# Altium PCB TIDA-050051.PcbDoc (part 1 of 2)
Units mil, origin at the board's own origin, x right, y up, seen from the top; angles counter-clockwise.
Board outline 1055.12 x 796.27 mil, 6 copper layers (Top Layer, Signal Layer 1, Signal Layer 2, Signal Layer 3, Signal Layer 4, Bottom Layer), stack 61 mil thick; 108 components, 65 nets, 370 pads, 157 vias.
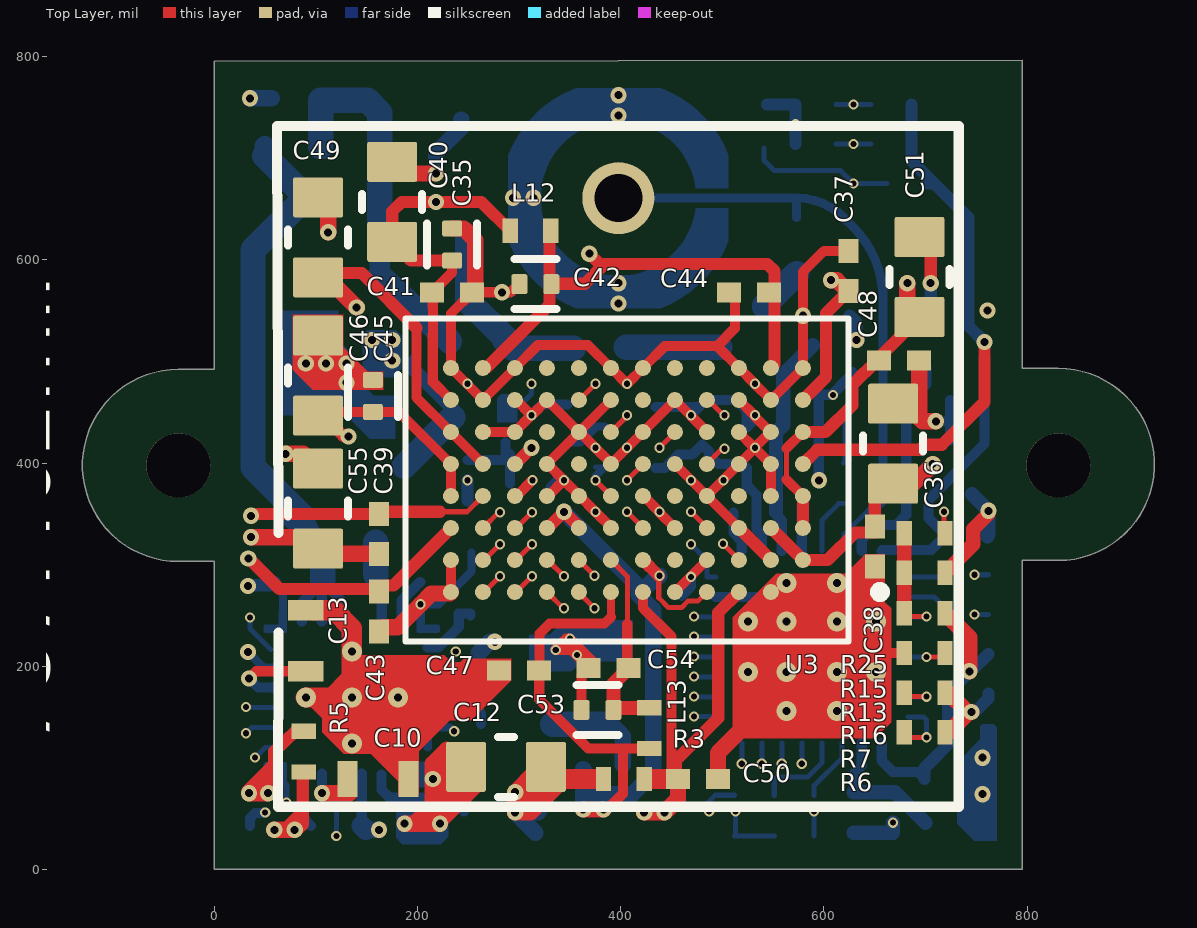
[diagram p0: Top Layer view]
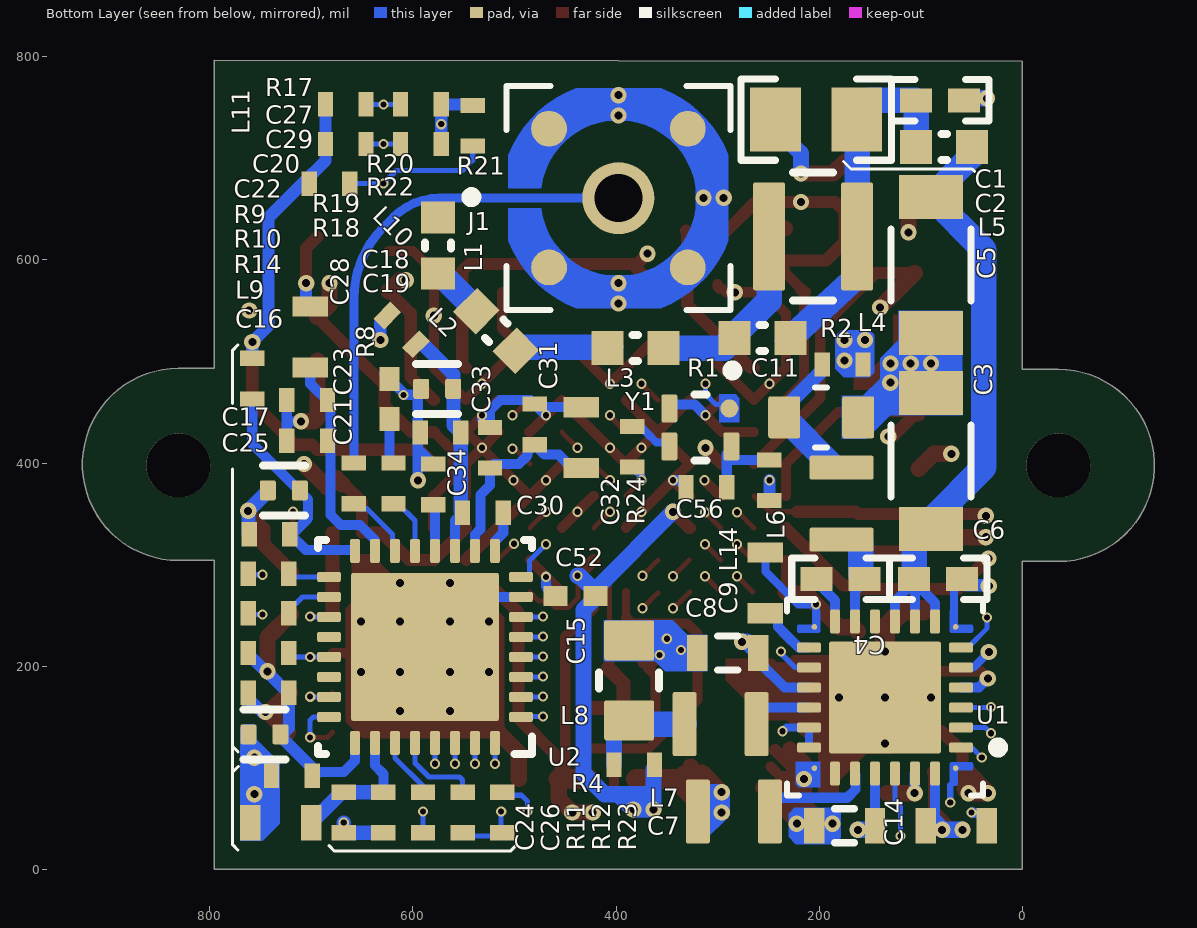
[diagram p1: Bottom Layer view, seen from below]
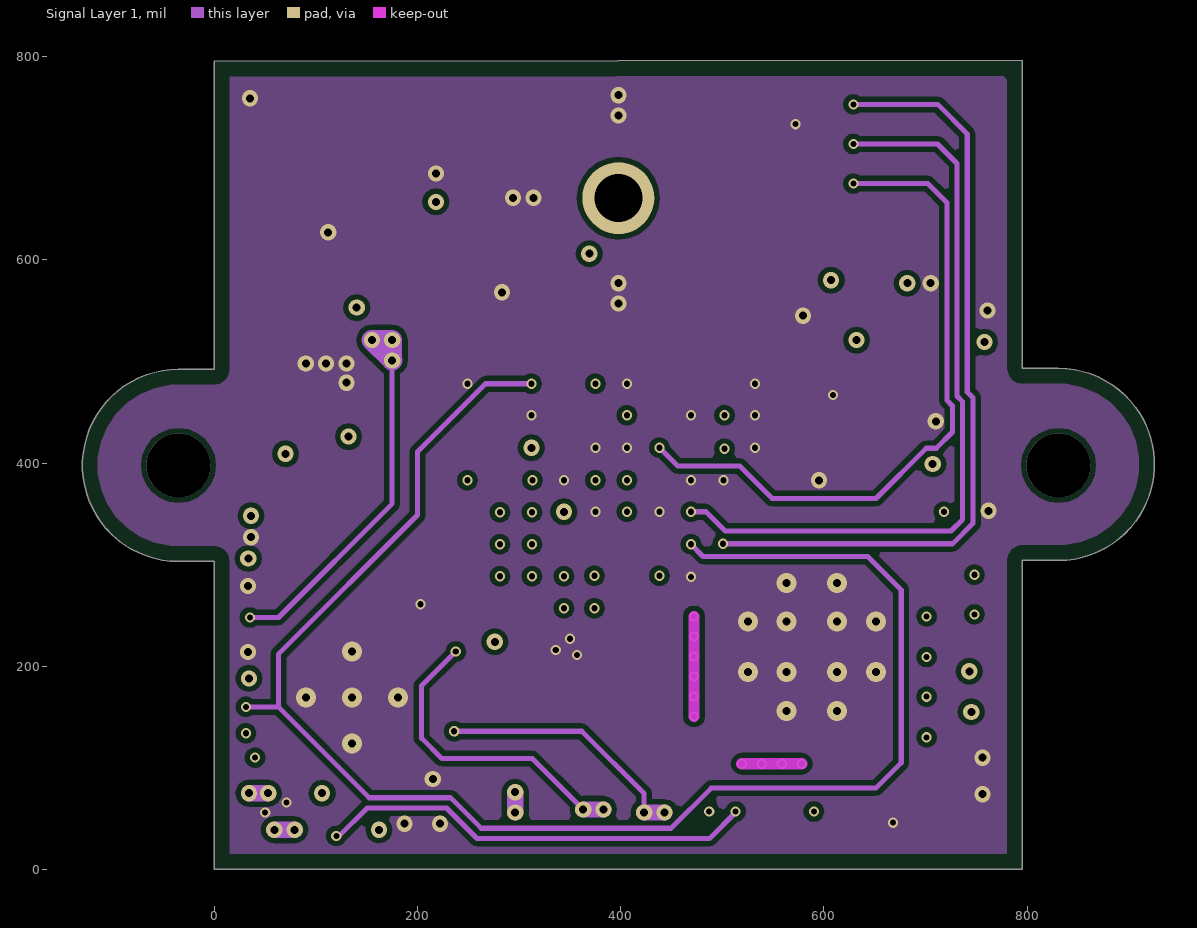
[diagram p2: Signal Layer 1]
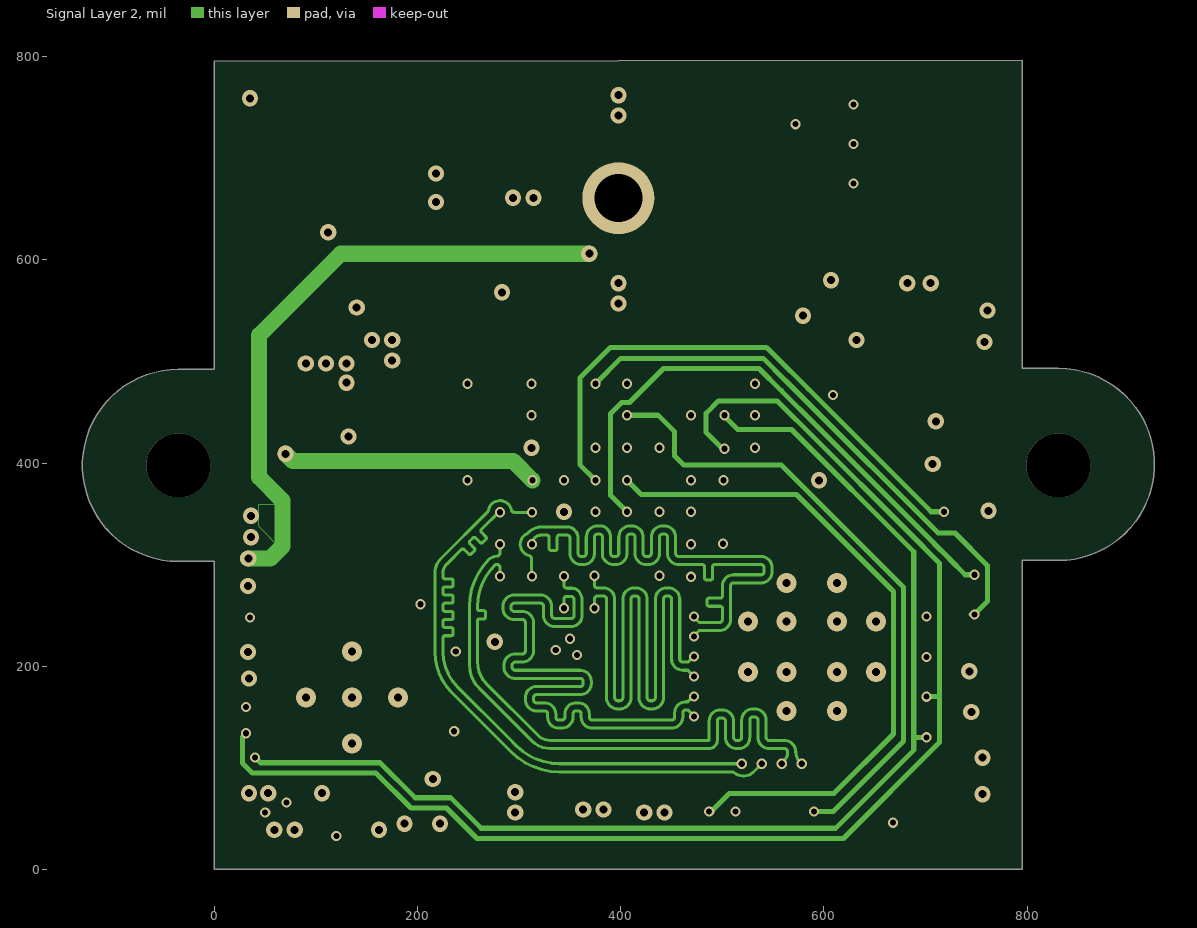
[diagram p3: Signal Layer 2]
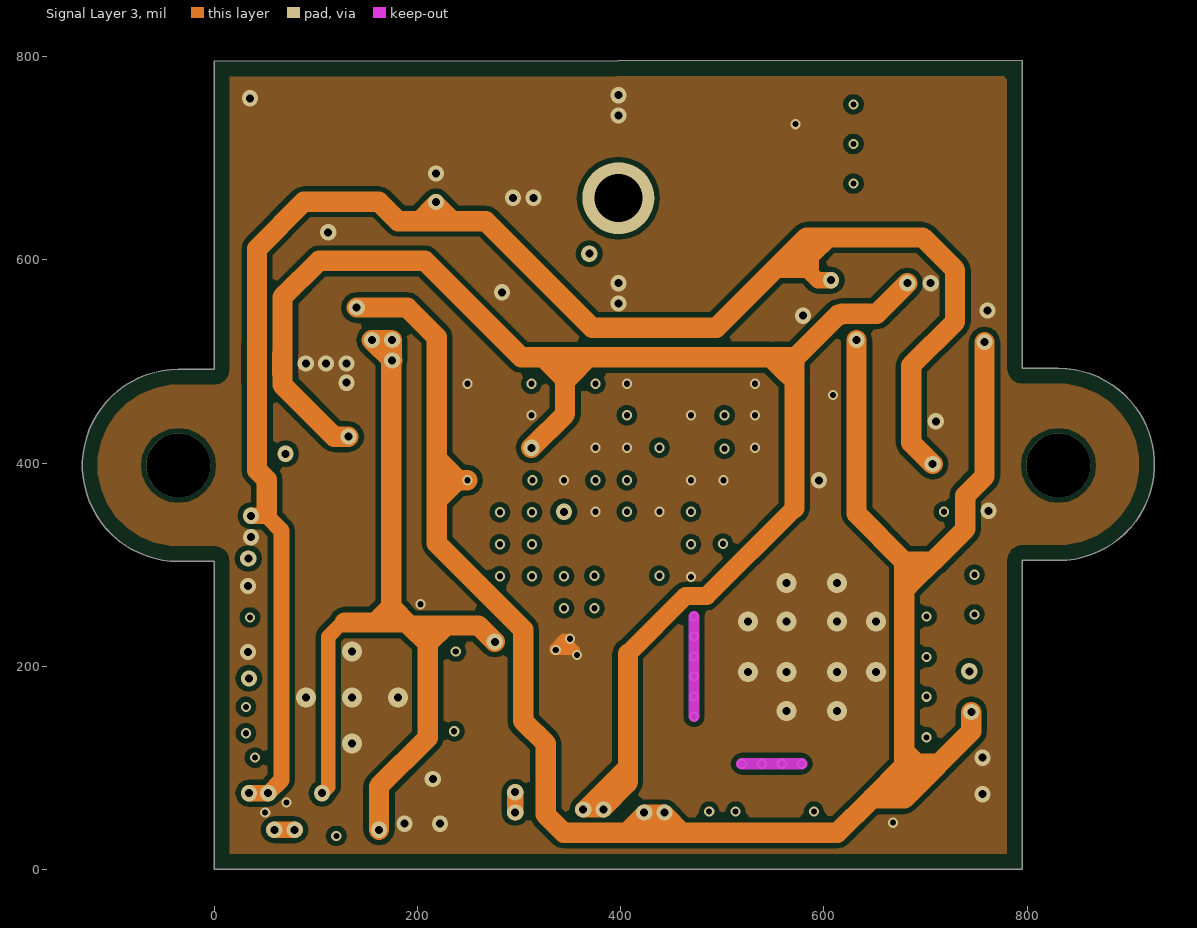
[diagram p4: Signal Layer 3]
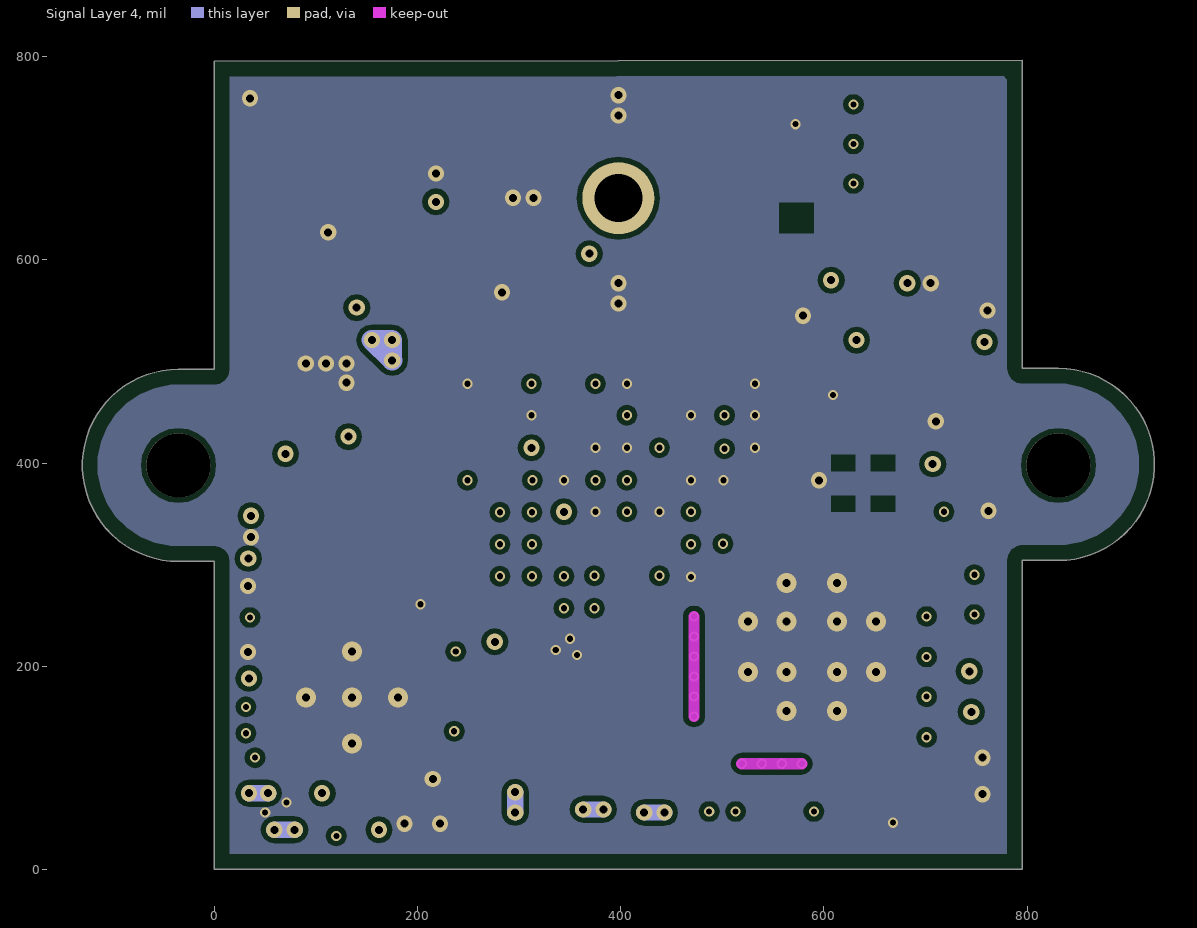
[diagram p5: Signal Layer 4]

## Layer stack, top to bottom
Top Solder: solder mask 0.5, Solder Resist, Dk 3.5
Top Layer: signal copper 1.4
Dielectric 1: prepreg 5.1, FR-4 High Tg, Dk 4.2
Signal Layer 1: signal copper 1.4
Dielectric 2: core 8, FR-4 High Tg, Dk 4.2
Signal Layer 2: signal copper 1.4
Dielectric 4: core 26.4, FR-4 High Tg, Dk 4.2
Signal Layer 3: signal copper 1.4
Dielectric 5: core 8, FR-4 High Tg, Dk 4.2
Signal Layer 4: signal copper 1.4
Dielectric 3: prepreg 5.1, FR-4 High Tg, Dk 4.2
Bottom Layer: signal copper 1.4
Bottom Solder: solder mask 0.5, Solder Resist, Dk 3.5

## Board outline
0,0 0,303.15 -35.43,303.15 cw(c-35.43,397.64) -35.43,492.13 0,492.13 0,795.28 795.28,796.27 795.28,493.11 830.71,493.11 cw(c830.71,398.62) 830.71,304.14 795.3,304.14 795.28,0.99 795.28,0

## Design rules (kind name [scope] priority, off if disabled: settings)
AcuteAngle [All] p1: minimum=4.50000000000000E+0001 checktracksonly=FALSE
AssemblyTestPointUsage [All] p1: valid=2
BoardOutlineClearance BoardOutlineClearance_MountingHoles [OnCopper and InComponentClass('Mounting Holes')] p1: gap=39.37 ignorepadtopadclearanceinfootprint=FALSE
BoardOutlineClearance BoardOutlineClearance_Poly [OnCopper and IsPoly] p2: gap=15 ignorepadtopadclearanceinfootprint=FALSE
BoardOutlineClearance [OnCopper and Not InComponentClass('Logo') and not InComponentClass('FiducialMark') and not InRegion(1000,500,4000,800) and not InPoly] p3: gap=25 ignorepadtopadclearanceinfootprint=FALSE
Clearance Clearance_Signal_Layer_1 [InPolygon And (OnLayer('Signal Layer 2'))] p1: gap=5 ignorepadtopadclearanceinfootprint=TRUE except(10: Arc-Arc Arc-Track Arc-SMDPad Arc-THPad Arc-Via Arc-Fill Arc-Poly Arc-Region Arc-Text Arc-Hole Track-Track Track-SMDPad Track-THPad Track-Via Track-Fill Track-Poly Track-Region Track-Text Track-Hole)
Clearance Clearance_Keepouts [((IsTrack Or IsArc) And Not InPoly) And IsFree and IsKeepOut vs ((IsTrack Or IsArc) And Not InPoly) And IsFree and IsKeepOut] p2: gap=0 ignorepadtopadclearanceinfootprint=FALSE
Clearance Clearance_Poly [InPolygon] p3: gap=5 ignorepadtopadclearanceinfootprint=TRUE
Clearance Clearance_FiducialMark [IsKeepOut and InComponentClass('FiducialMark') vs IsPad and InComponentClass('FiducialMark')] p4: gap=0 ignorepadtopadclearanceinfootprint=FALSE
Clearance [All] p5: gap=5 ignorepadtopadclearanceinfootprint=TRUE
ComponentClearance ComponentClearance_MountingHoles_FiducialMarks [InComponentClass('Mounting Holes') vs InComponentClass('FiducialMark')] p1: gap=50 collisioncheckmode=3 verticalgap=10 showdistances=FALSE
ComponentClearance ComponentClearance_Shunt [InComponentClass('Header') vs InComponentClass('Shunt')] p2: gap=0 collisioncheckmode=3 verticalgap=0 showdistances=FALSE
ComponentClearance ComponentClearance_Logo [InComponentClass('Logo')] p3: gap=30 collisioncheckmode=3 verticalgap=10 showdistances=FALSE
ComponentClearance ComponentClearance_ScrewToNut [(HasFootprint('NY PMS 440 0025 PH')) vs (HasFootprint('Keystone_1902C'))] p4: gap=5 collisioncheckmode=3 verticalgap=10 showdistances=FALSE
ComponentClearance ComponentClearance_MountingHoles [InComponentClass('Mounting Holes')] p5: gap=100 collisioncheckmode=3 verticalgap=100000 showdistances=FALSE
ComponentClearance ComponentClearance_SmallPassives [HasFootprint('0201*') or HasFootprint('0402*') or HasFootprint('0508') or HasFootprint('0603*') or HasFootprint('0612') or HasFootprint('0805*') or HasFootprint('0815*') or HasFootprint('0830*') or HasFootprint('1206*') or HasFootprint('1210*') or HasFootprint('1808*') or HasFootprint('1812*') or HasFootprint('1825*') or HasFootprint('2010*') or HasFootprint('2220*') or HasFootprint('2225*') or HasFootprint('2512*') or HasFootprint('2728*') or HasFootprint('3518*') vs HasFootprint('0201*') or HasFootprint('0402*') or HasFootprint('0508') or HasFootprint('0603*') or HasFootprint('0612') or HasFootprint('0805*') or HasFootprint('0815*') or HasFootprint('0830*') or HasFootprint('1206*') or HasFootprint('1210*') or HasFootprint('1808*') or HasFootprint('1812*') or HasFootprint('1825*') or HasFootprint('2010*') or HasFootprint('2220*') or HasFootprint('2225*') or HasFootprint('2512*') or HasFootprint('2728*') or HasFootprint('3518*')] p6: gap=14.96 collisioncheckmode=3 verticalgap=10 showdistances=FALSE
ComponentClearance ComponentClearance_THtoSMT [IsThruComponent vs IsSMTComponent] p7: gap=20 collisioncheckmode=3 verticalgap=30 showdistances=FALSE
ComponentClearance ComponentClearance_THtoTH [IsThruComponent vs IsThruComponent] p8: gap=20 collisioncheckmode=3 verticalgap=30 showdistances=FALSE
ComponentClearance [All] p9: gap=15 collisioncheckmode=3 verticalgap=10 showdistances=FALSE
DiffPairsRouting [All] p1: maxlimit=100 minlimit=5 mostfreqgap=10 toplayer_minwidth=3 toplayer_maxwidth=15 toplayer_prefwidth=5 midlayer1_minwidth=3 midlayer1_maxwidth=15 midlayer1_prefwidth=5 midlayer2_minwidth=3 midlayer2_maxwidth=15 midlayer2_prefwidth=5 midlayer3_minwidth=3 midlayer3_maxwidth=15 midlayer3_prefwidth=5 midlayer4_minwidth=3 midlayer4_maxwidth=15 midlayer4_prefwidth=5 bottomlayer_minwidth=3 bottomlayer_maxwidth=15 bottomlayer_prefwidth=5 maxuncoupledlength=1000
FabricationTestPointUsage TestPointUsage [All] p1: valid=2 allowmultiple=FALSE
FabricationTestpoint Testpoint [All] p1: side=3 testpointundercomponent=TRUE minsize=40 maxsize=100 preferedsize=60 minholesize=0 maxholesize=40 preferedholesize=32 testpointgrid=1 allowsidetop=TRUE allowsidebottom=TRUE usegrid=TRUE gridtolerance=0.01
FanoutControl Fanout_LCC [IsLCC] p1: bgadir=Out bgaviamode=Centered fanoutstyle=Auto fanoutdirection=Alternating viagrid=1 // Fanout_LCC (Default Rule)
FanoutControl Fanout_BGA [IsBGA] p2: bgadir=Out bgaviamode=Centered fanoutstyle=Auto fanoutdirection=Alternating viagrid=1 // Fanout_BGA (Default Rule)
FanoutControl Fanout_Default [All] p4: bgadir=Out bgaviamode=Centered fanoutstyle=Auto fanoutdirection=Alternating viagrid=1 // Fanout_Default (Default Rule)
FanoutControl Fanout_Small [(CompPinCount < 5)] p5: bgadir=Out bgaviamode=Centered fanoutstyle=Auto fanoutdirection=OutThenIn viagrid=1 // Fanout_Small (Default Rule)
HoleSize [All] p1: absolutevalues=TRUE maxlimit=251 minlimit=6 maxpercent=80.000 minpercent=20.000
MinimumAnnularRing MinimumAnnularRing_ThermalPadVias [IsVia and InAnyComponent] p1: minimumring=5.91
MinimumAnnularRing [All] p2: minimumring=2
MinimumSolderMaskSliver MinimumSolderMaskSliver_Logo [InComponentClass('Logo') vs InComponentClass('Logo')] p1: minsoldermaskwidth=0.7
MinimumSolderMaskSliver [All] p2: minsoldermaskwidth=3.94
PlaneConnect [All] p1: planeconnectstyle=Direct reliefexpansion=10 reliefentries=4 reliefconductorwidth=10 reliefairgap=10
PolygonConnect [All] p1: connectstyle=Direct reliefconductorwidth=10 reliefentries=4 polygonreliefangle="90 Angle" airgapwidth=10
RoutingVias ThermalPadVias [IsVia and InAnyComponent] p1: holewidth=7.87 width=19.68 viastyle="Through Hole" minholewidth=7.87 minwidth=19.68 maxholewidth=12.99 maxwidth=23.62
RoutingVias [All] p2: holewidth=16 width=34 viastyle="Through Hole" minholewidth=6 minwidth=10 maxholewidth=40 maxwidth=65
SilkToBoardRegionClearance [Not ((IsComment or IsDesignator) And (Hide <> 'False')) and not InRegion(1000,500,4000,800)] p1:
SilkToSilkClearance SilkToSilkClearance_Pb-FreeLogo [(HasFootprint('Pb-Free_Overlay_Medium') OR HasFootprint('Pb-Free_Overlay_Small')) vs (HasFootprint('Pb-Free_Overlay_Medium') OR HasFootprint('Pb-Free_Overlay_Small'))] p1: silktosilkclearance=0
SilkToSilkClearance [All] p2: silktosilkclearance=3
SilkToSolderMaskClearance SilkToComponentPadClearance [(IsPad or IsFill or IsRegion) and InAnycomponent] p1: minsilkscreentomaskgap=0 clearancetoexposedcopper=TRUE
SilkToSolderMaskClearance "Silk to Solder Mask Opening" [All] p2: minsilkscreentomaskgap=0 clearancetoexposedcopper=FALSE
SolderMaskExpansion [All] p1: expansion=1.97
UnRoutedNet [All] p1: checkbadconnections=TRUE
Width [All] p1: maxlimit=100 minlimit=5 preferedwidth=10 minimp=50.000000 maximp=50.000000 favimp=50.000000 checkconnectedcopper=TRUE
14 further rules are at their usual default settings.

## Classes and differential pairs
component class Serializer: C16 C17 C18 C19 C20 C21 C22 C23 C24 C25 C26 C27 C28 C29 C30 C31 C32 C33 C34 L9 L10 L11 R6 R7 R8 R9 R10 R11 R12 R13 R14 R15 R16 U2
component class Imager: C35 C36 C37 C38 C39 C40 C41 C42 C43 C44 C45 C46 C47 C48 C49 C50 C51 C52 C53 C54 C55 C56 L12 L13 L14 R17 R18 R19 R20 R21 R22 R23 R24 R25 U3 Y1
component class PMIC: C1 C2 C3 C4 C5 C6 C7 C8 C9 C10 C11 C12 C13 C14 C15 J1 L1 L2 L3 L4 L5 L6 L7 L8 R1 R2 R3 R4 R5 U1
component class Hardware: FID1 FID2 FID3 Logo2 ZZ1 ZZ2 ZZ3
component class FiducialMark: FID1 FID2 FID3
component class AssemblyNote: ZZ1 ZZ2 ZZ3
differential pair CSI0_D3: +CSI0_D3_P -CSI0_D3_N
differential pair CSI0_D2: +CSI0_D2_P -CSI0_D2_N
differential pair CSI0_D1: +CSI0_D1_P -CSI0_D1_N
differential pair CSI0_D0: +CSI0_D0_P -CSI0_D0_N
differential pair CSI0_CLK: +CSI0_CLK_P -CSI0_CLK_N

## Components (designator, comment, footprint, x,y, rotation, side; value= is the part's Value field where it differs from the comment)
C1 "Capacitor" 0805_HV 203,738 r0 bottom value=4.7uF
C2 "CGA2B3X7R1H104M050BB" 0402 81,757 r180 bottom value=0.1uF
C3 "C3216X7R1E106M160AE" 1206_190 90,402 r90 bottom value=10uF
C4 "CGA2B3X7R1H104M050BB" 0402 179,286 r0 bottom value=0.1uF
C5 "C1206C106J3RACAUTO" 1206_180 90,595 r270 bottom value=10uF
C6 "CGA2B3X7R1H104M050BB" 0402 83,286 r180 bottom value=0.1uF
C7 "GRM188Z71A106KA73D" 0603S 175,43 r0 bottom
C8 "GRM188Z71A106KA73D" 0603S 290,213 r0 bottom
C9 "LMK107B7105KAHT" 0603S 253,282 r270 bottom value=1uF
C10 "GCM188R70J225KE22D" 0603S 161,89 r0 top value=2.2uF
C11 "CGA4J3X7S1A106K125AE" FP-CGA4J3X7S1A106K125AE_0805-MFG 198,445 r0 bottom
C12 "JMJ212CB7106KGHT" 0805_HV1 287,101 r180 top value=10uF
C13 "LMK107B7105KAHT" 0603S 90,225 r90 top value=1uF
C14 "GCM188R70J225KE22D" 0603S 65,43 r180 bottom value=2.2uF
C15 "JMJ212CB7106KGHT" 0805_HV1 387,186 r90 bottom value=10uF
C16 "GRT155R70J105KE01D" FP-GRT155R70J105KE01D_0402-MFG 746,133 r180 bottom
C17 "GRM155R71C103KA01D" 0402S 719,92 r0 bottom value=0.01uF
C18 "GRT155R70J105KE01D" FP-GRT155R70J105KE01D_0402-MFG 576,473 r180 bottom
C19 "GRM155R71C103KA01D" 0402S 572.72,430 r0 bottom value=0.01uF
C20 "GRT155R70J105KE01D" FP-GRT155R70J105KE01D_0402-MFG 727,373 r180 bottom
C21 "CGA2B3X7R1H333K050BB" 0402S 658,380 r270 bottom value=0.033uF
C22 "GRM155R71C103KA01D" 0402S 741,330 r0 bottom value=0.01uF
C23 "CGA2B3X7R1H153K050BB" 0402S 619,380 r270 bottom value=0.015uF
C24 "0402YC104KAT2A" 0402S 668,56 r270 bottom value=0.1uF
C25 "GRM188Z71A106MA73D" 0603S 730,46 r180 bottom value=10uF
C26 "GRM155R71C103KA01D" 0402S 629,56 r270 bottom value=0.01uF
C27 "0402YC104KAT2A" 0402S 704,462 r0 bottom value=0.1uF
C28 "GRM188Z71A106MA73D" 0603S 701,524 r270 bottom value=10uF
C29 "GRM155R71C103KA01D" 0402S 704,422 r0 bottom value=0.01uF
C30 "GRM155R70J223KA01D" 0402S 531,351 r180 bottom value=0.022uF
C31 "0402YC104KAT2A" 0402S 480,438 r90 bottom value=0.1uF
C32 "GRM188Z71A106MA73D" 0603S 434,425 r270 bottom value=10uF
C33 "GRM155R71C103KA01D" 0402S 524,415 r90 bottom value=0.01uF
C34 "0402YC104KAT2A" 0402S 580,379 r90 bottom value=0.1uF
C35 "GRT155R70J105KE01D" FP-GRT155R70J105KE01D_0402-MFG 234,615 r270 top
C36 "GCJ21BR71A106KE01L" 0805_HV1 668,419 r90 top value=10uF
C37 "GRM155R71E104KE14D" 0402L 624,589 r90 top value=0.1uF
C38 "GRM155R71E104KE14D" 0402L 650,318 r270 top value=0.1uF
C39 "GRM155R71E104KE14D" 0402L 162,330 r270 top value=0.1uF
C40 "GCJ21BR71A106KE01L" 0805_HV1 175,657 r90 top value=10uF
C41 "GRM155R71E104KE14D" 0402L 234,568 r0 top value=0.1uF
C42 "GRT155R70J105KE01D" FP-GRT155R70J105KE01D_0402-MFG 316,576 r0 top
C43 "GRM155R71E104KE14D" 0402L 162,254 r270 top value=0.1uF
C44 "GRM155R71E104KE14D" 0402L 526,568 r180 top value=0.1uF
C45 "GRT155R70J105KE01D" FP-GRT155R70J105KE01D_0402-MFG 156,466 r270 top
C46 "GCJ21BR71A106KE01L" 0805_HV1 102,486 r90 top value=10uF
C47 "GRM155R71E104KE14D" 0402L 300,196 r180 top value=0.1uF
C48 "GRM155R71E104KE14D" 0402L 674,501 r0 top value=0.1uF
C49 "GCJ21BR71A106KE01L" 0805_HV1 102,622 r90 top value=10uF
C50 "GRM155R71E104KE14D" 0402L 476,89 r0 top value=0.1uF
C51 "GCJ21BR71A106KE01L" 0805_HV1 694,583 r90 top value=10uF
C52 "GRM155R71E104KE14D" 0402L 440,269 r0 bottom value=0.1uF
C53 "GRT155R70J105KE01D" FP-GRT155R70J105KE01D_0402-MFG 377,157 r0 top
C54 "GRM155R71E104KE14D" 0402L 388,198 r180 top value=0.1uF
C55 "GCJ21BR71A106KE01L" 0805_HV1 102,355 r270 top value=10uF
C56 "GCM155R71C104KA55D" 0402S 311,376 r0 bottom value=0.1uF
FID1 "Fiducial" Fiducial10-20 3245,180 r0 top
FID2 "Fiducial" Fiducial10-20 3038.84,180.94 r0 top
FID3 "Fiducial" Fiducial10-20 3499,173 r0 top
J1 "59S13X-40MT5" FP-59S13X-40MT5_FAKRA_HF_STR_PLUG-MFG 397.64,660.72 r180 bottom
L1 "BLM18HE152SN1D" 0603L 575,614 r270 bottom value="1500 ohm"
L2 "BLM18HE152SN1D" 0603L 518,530 r225 bottom value="1500 ohm"
L3 "BLM18HE152SN1D" 0603L 381,513 r180 bottom value="1500 ohm"
L4 "LQH3NPZ100MJRL" LQH3NPZ_JR 206,623 r0 bottom value=10uH
L5 "BLM18AG102SN1D" 0603L 77,711 r180 bottom value="1000 ohm"
L6 "TFM201610ALMA1R5MTAA" TFM201610ALMA 178,360 r90 bottom value=1.5uH
L7 "TFM201610ALMA1R0MTAA" TFM201610ALMA 284,57 r0 bottom value=1uH
L8 "TFM201610ALMA1R0MTAA" TFM201610ALMA 297,143 r0 bottom value=1uH
L9 "BLM15AX102SN1D" 0402S 742,174 r180 bottom value="1000 ohm"
L10 "BLM15AX102SN1D" 0402S 611,531 r225 bottom value="1000 ohm"
L11 "BLM15AX102SN1D" 0402S 758,483 r270 bottom value="1000 ohm"
L12 "BLM15HD601SN1D" 0402S 311.09,628.63 r0 top value="600 ohm"
L13 "BLM15HD601SN1D" 0402S 428,139 r90 top value="600 ohm"
L14 "BLM15AG221SN1D" 0402S 249,383 r90 bottom value="220 ohm"
Logo1 "Texas Instruments" TI_Symbol_Overlay_Small 2843,833 r180 bottom
Logo2 "FCC disclaimer" FCC_disclaimer 3153,23 r0 top
R1 "CRCW06034K02FKEA" 0603L 256,523 r0 bottom value=4.02k
R2 "Resistor" 0402S 177,497 r180 bottom value=0
R3 "Resistor" 0402S 403,89 r0 top value=0
R4 "Resistor" 0402S 382,103 r180 bottom value=0
R5 "Resistor" 0402S 88,116 r90 top value=0
R6 "CRCW04021K50JNED" 0402S 699,135 r0 top value=1.5k
R7 "CRCW04021K50JNED" 0402S 699,174 r0 top value=1.5k
R8 "CRCW040249R9FKED" 0402L 623,463 r270 bottom value=49.9
R9 "CRCW04020000Z0ED" 0402S 742,291 r180 bottom value=0
R10 "CRCW04020000Z0ED" 0402S 742,252 r180 bottom value=0
R11 "CRCW04020000Z0ED" 0402S 590,56 r90 bottom value=0
R12 "CRCW04020000Z0ED" 0402S 551,56 r90 bottom value=0
R13 "CRCW04020000Z0ED" 0402S 699,252 r0 top value=0
R14 "CRCW040210K0JNED" 0402S 742,213 r0 bottom value=10k
R15 "CRCW040240K2FKED" 0402S 699,292 r180 top value=40.2k
R16 "CRCW0402402RFKED" 0402S 699,213 r0 top value=402
R17 "CRCW04020000Z0ED" 0402S 666,753 r0 bottom value=0
R18 "CRCW04020000Z0ED" 0402S 682,675 r0 bottom value=0
R19 "CRCW04020000Z0ED" 0402S 666,714 r0 bottom value=0
R20 "CRCW04020000Z0ED" 0402S 592,753 r0 bottom value=0
R21 "CRCW04020000Z0ED" 0402S 541,732 r270 bottom value=0
R22 "CRCW04020000Z0ED" 0402S 592,714 r0 bottom value=0
R23 "CRCW04020000Z0ED" 0402S 512,56 r90 bottom value=0
R24 "ERJ-2GEJ220X" 0402S 384,416 r270 bottom value=22
R25 "ERJ-2GE0R00X" 0402S 699,331 r0 top value=0
U1 "TPS65033000RGERQ1" RGE0024K-MFG 135.21,169.2 r0 bottom
U2 "DS90UB953TRHBRQ1" RHB0032P 588,219 r0 bottom
U3 "AR0820AT1B18XMEA0-DPBR-E" FP-AR0820AT1B18XMEA0-DPBR-E_iBGA95-MFG 406.05,383.26 r180 top
Y1 "DSC6101MI2A-024.0000T" FP-DSC6101MI2A-024.0000T_VFLGA4-0 317,435 r0 bottom
ZZ1 "These assemblies are ESD sensitive, ESD precautions shall be observed." AssemblyNote 185,3829.11 r0 top
ZZ2 "These assemblies must be clean and free from flux and all contaminants. Use of no clean flux is not acceptable." AssemblyNote 185,3740.56 r0 top
ZZ3 "These assemblies must comply with workmanship standards IPC-A-610 Class 2, unless otherwise specified." AssemblyNote 185,3652 r0 top

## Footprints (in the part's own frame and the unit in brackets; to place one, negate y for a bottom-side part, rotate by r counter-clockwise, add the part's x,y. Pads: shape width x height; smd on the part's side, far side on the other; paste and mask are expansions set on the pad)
0402 [mm] "0402 from SM-752 data"
  rect 0.8x0.6 smd: 1(-0.6,0) 2(0.6,0)
  silkscreen extent -1.22,-0.52 1.22,0.52, body extent -0.55,-0.3 0.55,0.3, height 0.6
0402L [mm] "0402 from SM-752 data"
  rect 0.6x0.5 smd: 1(-0.5,0) 2(0.5,0)
  body extent -0.55,-0.3 0.55,0.3, height 0.6
0402S [mil] "Based on C0402S footprint from PADS legacy"
  rect 15x24 smd: 1(-20,0) 2(20,0)
  body extent -22,-12 22,12, height 24
0603L [mm] "0603 from SM-752 data"
  rect 0.8x0.85 smd: 1(-0.7,0) 2(0.7,0)
  silkscreen extent -0.07,-0.33 0.07,0.33, body extent -0.87,-0.47 0.87,0.47, height 1
0603S [mil]
  rect 20x35 smd: 1(-30,0) 2(30,0)
  silkscreen extent -10,-17 10,17, body extent -34,-19 34,19, height 39
0805_HV [mil] "0805 with 30mil clearance between pads"
  rect 50x63 smd: 1(-40,0) 2(40,0)
  silkscreen extent -74,-40 74,40, body extent -43,-29 43,29, height 57
0805_HV1 [mm] "Custom footprint based on analyzing multiple manufacturer recommendations"
  rrect10% 1x1.25 smd: 1(-1,0) 2(1,0)
  silkscreen extent -0.2,-0.75 0.2,0.75, body extent -1.1,-0.72 1.1,0.73, height 1.45
1206_180 [mm] "1206_180"
  rect 1.1x1.6 smd: 1(-1.7,0) 2(1.7,0)
  silkscreen extent -0.9,-1 0.9,1, body extent -1.75,-0.95 1.75,0.95, height 1.8
1206_190 [mm] "1206_190"
  rect 1.1x1.6 smd: 1(-1.7,0) 2(1.7,0)
  silkscreen extent -0.9,-1 0.9,1, body extent -1.75,-0.95 1.75,0.95, height 1.9
AssemblyNote [mil] "Assembly Note"
FCC_disclaimer [mil]
Fiducial10-20 [mm]
  round 1 smd mask+0.5: 1(0,0)
  Top Layer keep-out circle w1.178: c0,0 r0.5
FP-59S13X-40MT5_FAKRA_HF_STR_PLUG-MFG [mm]
  round 1.8 hole 1.2 paste-1000 mask+0: 1(0,0)
  round 0.895 smd paste+0 mask+0: 2(-1.734,1.734) 3(1.734,1.734) 4(-1.734,-1.734) 5(1.734,-1.734)
  Top Layer region: -0.25,-2.75 -0.25,-1.934 -1.046,-1.645 -1.645,-1.046 -1.934,-0.25 -1.934,-0.25 -2.75,-0.25 -2.75,-1.068 -2.086,-2.086 -1.068,-2.75 -1.068,-2.75
  Top Layer region: 0.25,-2.75 0.25,-1.934 1.046,-1.645 1.645,-1.046 1.934,-0.25 1.934,-0.25 2.75,-0.25 2.75,-1.068 2.086,-2.086 1.068,-2.75 1.068,-2.75
  Top Layer region: 0.25,2.75 0.25,1.934 1.046,1.645 1.645,1.046 1.934,0.25 1.934,0.25 2.75,0.25 2.75,1.068 2.086,2.086 1.068,2.75 1.068,2.75
  Top Layer region: -0.25,2.75 -0.25,1.934 -1.046,1.645 -1.645,1.046 -1.934,0.25 -1.934,0.25 -2.75,0.25 -2.75,1.068 -2.086,2.086 -1.068,2.75 -1.068,2.75
  silkscreen extent -3.8,-2.8 2.8,2.8, body extent -3.75,-3.75 3.75,3.75, height 14.8
FP-AR0820AT1B18XMEA0-DPBR-E_iBGA95-MFG [mm]
  round 0.4 smd paste+0 mask+0: A2(-3.6,2.8) A3(-2.8,2.8) A4(-2,2.8) A5(-1.2,2.8) A6(-0.4,2.8) A7(0.4,2.8) A8(1.2,2.8) A9(2,2.8) A10(2.8,2.8) A11(3.6,2.8) A12(4.4,2.8) B1(-4.4,2) B2(-3.6,2) B3(-2.8,2) B4(-2,2) B5(-1.2,2) B6(-0.4,2) B7(0.4,2) B8(1.2,2) B9(2,2) B10(2.8,2) B11(3.6,2) B12(4.4,2) C1(-4.4,1.2) C2(-3.6,1.2) C3(-2.8,1.2) C4(-2,1.2) C5(-1.2,1.2) C6(-0.4,1.2) C7(0.4,1.2) C8(1.2,1.2) C9(2,1.2) C10(2.8,1.2) C11(3.6,1.2) C12(4.4,1.2) D1(-4.4,0.4) D2(-3.6,0.4) D3(-2.8,0.4) D4(-2,0.4) D5(-1.2,0.4) D6(-0.4,0.4) D7(0.4,0.4) D8(1.2,0.4) D9(2,0.4) D10(2.8,0.4) D11(3.6,0.4) D12(4.4,0.4) E1(-4.4,-0.4) E2(-3.6,-0.4) E3(-2.8,-0.4) E4(-2,-0.4) E5(-1.2,-0.4) E6(-0.4,-0.4) E7(0.4,-0.4) E8(1.2,-0.4) E9(2,-0.4) E10(2.8,-0.4) E11(3.6,-0.4) E12(4.4,-0.4) F1(-4.4,-1.2) F2(-3.6,-1.2) F3(-2.8,-1.2) F4(-2,-1.2) F5(-1.2,-1.2) F6(-0.4,-1.2) F7(0.4,-1.2) F8(1.2,-1.2) F9(2,-1.2) F10(2.8,-1.2) F11(3.6,-1.2) F12(4.4,-1.2) G1(-4.4,-2) G2(-3.6,-2) G3(-2.8,-2) G4(-2,-2) G5(-1.2,-2) G6(-0.4,-2) G7(0.4,-2) G8(1.2,-2) G9(2,-2) G10(2.8,-2) G11(3.6,-2) G12(4.4,-2) H1(-4.4,-2.8) H2(-3.6,-2.8) H3(-2.8,-2.8) H4(-2,-2.8) H5(-1.2,-2.8) H6(-0.4,-2.8) H7(0.4,-2.8) H8(1.2,-2.8) H9(2,-2.8) H10(2.8,-2.8) H11(3.6,-2.8) H12(4.4,-2.8)
  silkscreen extent -6.45,-4.04 5.54,4.04, body extent -6.04,-4.54 6.04,4.54, height 0.25
FP-CGA4J3X7S1A106K125AE_0805-MFG [mm]
  rrect13% 0.8x1.05 smd paste+0 mask+0: 1(-0.925,0) 2(0.925,0)
  silkscreen extent -0.15,-0.75 0.15,0.75, body extent -1.2,-0.62 1.2,0.63, height 1.5
FP-DSC6101MI2A-024.0000T_VFLGA4-0 [mm]
  round 0.45 smd paste+0 mask+0: 1(-0.725,-0.475)
  rrect25% 0.4x0.7 smd paste+0 mask+0: 2(0.775,-0.475) 3(0.775,0.475) 4(-0.775,0.475)
  Top Layer region: -0.975,-0.125 -0.475,-0.125 -0.475,-0.825 -0.883,-0.825 -0.975,-0.733
  silkscreen extent -0.92,-1.55 0.15,0.82, body extent -1,-0.8 1,0.8, height 0.89
FP-GRT155R70J105KE01D_0402-MFG [mm]
  rrect25% 0.4x0.5 smd paste+0 mask+0: 1(-0.4,0) 2(0.4,0)
  silkscreen extent -0.53,-0.63 0.53,0.63, body extent -0.5,-0.25 0.5,0.25, height 0.55
LQH3NPZ_JR [mm] "SMD, 2-Leads, Body 3x3mm"
  rrect12% 0.8x2.7 smd: 1(-1.1,0) 2(1.1,0)
  silkscreen extent -0.5,-1.6 0.5,1.6, body extent -1.6,-1.6 1.6,1.6, height 1.2
RGE0024K-MFG [mm]
  rrect40% 0.6x0.25 smd paste+0 mask+0: 1(-1.9,1.25) 2(-1.9,0.75) 3(-1.9,0.25) 4(-1.9,-0.25) 5(-1.9,-0.75) 6(-1.9,-1.25) 13(1.9,-1.25) 14(1.9,-0.75) 15(1.9,-0.25) 16(1.9,0.25) 17(1.9,0.75) 18(1.9,1.25)
  rrect40% 0.25x0.6 smd paste+0 mask+0: 7(-1.25,-1.9) 8(-0.75,-1.9) 9(-0.25,-1.9) 10(0.25,-1.9) 11(0.75,-1.9) 12(1.25,-1.9) 19(1.25,1.9) 20(0.75,1.9) 21(0.25,1.9) 22(-0.25,1.9) 23(-0.75,1.9) 24(-1.25,1.9)
  rrect4% 2.8x2.8 smd paste-1000 mask+0: 25(0,0)
  round 0.14 smd paste+0 mask+0: A1(-1.765,1.765) A2(-1.765,-1.765) A3(1.765,-1.765) A4(1.765,1.765)
  Top Layer region: -1.62,2.15 -1.627,2.175 -1.645,2.193 -1.67,2.2 -1.67,2.2 -1.77,2.2 -1.795,2.193 -1.813,2.175 -1.82,2.15 -1.82,2.15 -1.82,1.82 -2.15,1.82 -2.175,1.813 -2.193,1.795 -2.2,1.77 -2.2,1.77 -2.2,1.67 -2.193,1.645 -2.175,1.627 -2.15,1.62 -2.15,1.62 -1.67,1.62 -1.651,1.624 -1.635,1.635 -1.624,1.651 -1.62,1.67 -1.62,1.67
  Top Layer region: 1.62,-2.15 1.627,-2.175 1.645,-2.193 1.67,-2.2 1.67,-2.2 1.77,-2.2 1.795,-2.193 1.813,-2.175 1.82,-2.15 1.82,-2.15 1.82,-1.82 2.15,-1.82 2.175,-1.813 2.193,-1.795 2.2,-1.77 2.2,-1.77 2.2,-1.67 2.193,-1.645 2.175,-1.627 2.15,-1.62 2.15,-1.62 1.67,-1.62 1.651,-1.624 1.635,-1.635 1.624,-1.651 1.62,-1.67 1.62,-1.67
  Top Layer region: -2.15,-1.62 -2.175,-1.627 -2.193,-1.645 -2.2,-1.67 -2.2,-1.67 -2.2,-1.77 -2.193,-1.795 -2.175,-1.813 -2.15,-1.82 -2.15,-1.82 -1.82,-1.82 -1.82,-2.15 -1.813,-2.175 -1.795,-2.193 -1.77,-2.2 -1.77,-2.2 -1.67,-2.2 -1.645,-2.193 -1.627,-2.175 -1.62,-2.15 -1.62,-2.15 -1.62,-1.67 -1.624,-1.651 -1.635,-1.635 -1.651,-1.624 -1.67,-1.62 -1.67,-1.62
  Top Layer region: 2.15,1.62 2.175,1.627 2.193,1.645 2.2,1.67 2.2,1.67 2.2,1.77 2.193,1.795 2.175,1.813 2.15,1.82 2.15,1.82 1.82,1.82 1.82,2.15 1.813,2.175 1.795,2.193 1.77,2.2 1.77,2.2 1.67,2.2 1.645,2.193 1.627,2.175 1.62,2.15 1.62,2.15 1.62,1.67 1.624,1.651 1.635,1.635 1.651,1.624 1.67,1.62 1.67,1.62
  silkscreen extent -2.95,-2.45 2.45,2.45, body extent -2,-2 2,2, height 1
RHB0032P [mm] "QFN, 32-Leads, Body 5x5mm, Pitch 0.5mm, Thermal Pad 3.7x3.7mm"
  rrect40% 0.6x0.25 smd: 1(-2.4,1.75) 2(-2.4,1.25) 3(-2.4,0.75) 4(-2.4,0.25) 5(-2.4,-0.25) 6(-2.4,-0.75) 7(-2.4,-1.25) 8(-2.4,-1.75) 17(2.4,-1.75) 18(2.4,-1.25) 19(2.4,-0.75) 20(2.4,-0.25) 21(2.4,0.25) 22(2.4,0.75) 23(2.4,1.25) 24(2.4,1.75)
  rrect40% 0.25x0.6 smd: 9(-1.75,-2.4) 10(-1.25,-2.4) 11(-0.75,-2.4) 12(-0.25,-2.4) 13(0.25,-2.4) 14(0.75,-2.4) 15(1.25,-2.4) 16(1.75,-2.4) 25(1.75,2.4) 26(1.25,2.4) 27(0.75,2.4) 28(0.25,2.4) 29(-0.25,2.4) 30(-0.75,2.4) 31(-1.25,2.4) 32(-1.75,2.4)
  rrect9% 1.06x1.06 on Bottom Paste: 33(-1.26,-1.26) 33(-1.26,0) 33(-1.26,1.26) 33(0,-1.26) 33(0,0) 33(0,1.26) 33(1.26,-1.26) 33(1.26,0) 33(1.26,1.26)
  rrect3% 3.7x3.7 smd paste-1.85: 33(0,0)
  silkscreen extent -2.67,-2.68 2.67,2.68, body extent -2.5,-2.5 2.5,2.5, height 1
TFM201610ALMA [mm] "TDK"
  rrect17% 0.6x1.6 smd: 1(-0.9,0) 2(0.9,0)
  body extent -1.1,-0.9 1.1,0.9, height 1
TI_Symbol_Overlay_Small [mil]
  silkscreen extent -90,-88 91,88

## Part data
C1: library part CMP-0007870-2, "CAP, CERM, 4.7 uF, 25 V, +/- 10%, X7R, 0805", Cap_Case=0805, Manufacturer=TDK, PartNumber=C2012X7R1E475K125AB, Supplier Part Number 1=445-5972-1-ND, TempCo=X7R, Tolerance_%=10%, Value1=Unknown, Value2=25V, ValueDisplayed=4.7uF
C2 C4 C6: library part CMP-0006326-2, "CAP, CERM, 0.1 uF, 50 V, +/- 20%, X7R, AEC-Q200 Grade 1, 0402", Cap_Case=0402, Manufacturer=TDK, Supplier Part Number 1=445-12271-1-ND, TempCo=X7R, Tolerance_%=20%, Value1=Unknown, Value2=50V, ValueDisplayed=0.1uF
C3: library part CMP-0008692-2, "CAP, CERM, 10 uF, 25 V, +/- 20%, X7R, 1206_190", Cap_Case=1206, Manufacturer=TDK, Supplier Part Number 1=445-6812-1-ND, TempCo=X7R, Tolerance_%=20%, Value1=Unknown, Value2=25V, ValueDisplayed=10uF
C5: library part CMP-0081062-1, "CAP, CERM, 10 µF, 25 V,+/- 5%, X7R, AEC-Q200 Grade 1, 1206", Cap_Case=1206_180, Manufacturer=Kemet, Supplier Part Number 1=399-15734-1-ND, TempCo=X7R, Tolerance_%=5%, Value2=25V, ValueDisplayed=10µF
C7 C8: library part CMP-0087107-2, "Chip Multilayer Ceramic Capacitors for General Purpose", Manufacturer=Murata, TempCo=15%, Tolerance_%=10%
C9 C13: library part CMP-0007505-4, "CAP, CERM, 1 uF, 10 V, +/- 10%, X7R, AEC-Q200 Grade 1, 0603", Cap_Case=0603, Manufacturer="Taiyo Yuden", Supplier Part Number 1=587-3410-1-ND, TempCo=X7R, Tolerance_%=10%, Value1=Unknown, Value2=10V, ValueDisplayed=1uF
C10 C14: library part CMP-0007134-5, "CAP, CERM, 2.2 uF, 6.3 V, +/- 10%, X7R, AEC-Q200 Grade 1, 0603", Cap_Case=0603, Manufacturer=MuRata, Supplier Part Number 1=490-5316-1-ND, TempCo=X7R, Tolerance_%=10%, Value1=Unknown, Value2=6.3V, ValueDisplayed=2.2uF
C11: library part CMP-0089543-1, "10µF ±10% 10V Ceramic Capacitor X7S 0805 (2012 Metric)", Digikey Part Number=445-173805-1-ND, Manufacturer=TDK, Mouser Part Number=810-CG4J3X7S1A106KAE, Operating Temperature Range="-55°C to +125°C", TempCo=22%, Temperature Characteristic=X7S, Tolerance_%=10%, ValueDisplayed=10uF
C12 C15: library part CMP-0081188-1, "CAP, CERM, 10 µF, 6.3 V,+/- 10%, X7R, AEC-Q200 Grade 1, 0805", Cap_Case=0805, Manufacturer="Taiyo Yuden", Supplier Part Number 1=587-4357-1-ND, TempCo=X7R, Tolerance_%=10%, Value2=6.3V, ValueDisplayed=10µF
C16 C18 C20 C35 C42 C45 C53: library part CMP-0088425-1, "1µF ±10% 6.3V Ceramic Capacitor X7R 0402 (1005 Metric)", Digikey Part Number=490-18216-1-ND, Manufacturer=Murata, Mouser Part Number=81-GRT155R70J105KE1D, Operating Temperature Range="-55°C to +125°C", TempCo=15%, Temperature Characteristic=X7R, Tolerance_%=10%, ValueDisplayed=1uF
C17 C19 C22 C26 C29 C33: library part CMP-0006639-2, "CAP, CERM, 0.01 uF, 16 V, +/- 10%, X7R, 0402", Cap_Case=0402, Manufacturer=MuRata, Supplier Part Number 1=490-1313-1-ND, TempCo=X7R, Tolerance_%=10%, Value1=Unknown, Value2=16V, ValueDisplayed=0.01uF
C21: library part CMP-0006329-2, "CAP, CERM, 0.033 uF, 50 V, +/- 10%, X7R, AEC-Q200 Grade 1, 0402", Cap_Case=0402, Manufacturer=TDK, Supplier Part Number 1=445-6896-1-ND, TempCo=X7R, Tolerance_%=10%, Value1="0.098477 ohm", Value2=50V, ValueDisplayed=0.033uF
C23: library part CMP-0006327-2, "CAP, CERM, 0.015 uF, 50 V, +/- 10%, X7R, AEC-Q200 Grade 1, 0402", Cap_Case=0402, Manufacturer=TDK, Supplier Part Number 1=445-6894-1-ND, TempCo=X7R, Tolerance_%=10%, Value1="0.2162 ohm", Value2=50V, ValueDisplayed=0.015uF
C24 C27 C31 C34: library part CMP-0006201-2, "CAP, CERM, 0.1 uF, 16 V, +/- 10%, X7R, 0402", Cap_Case=0402, Manufacturer=AVX, Supplier Part Number 1=478-7888-1-ND, TempCo=X7R, Tolerance_%=10%, Value1=Unknown, Value2=16V, ValueDisplayed=0.1uF
C25 C28 C32: library part CMP-0007497-5, "CAP, CERM, 10 uF, 10 V, +/- 20%, X7R, 0603", Cap_Case=0603, Manufacturer=MuRata, Supplier Part Number 1=81-GRM188Z71A106MA3D, TempCo=X7R, Tolerance_%=20%, Value1=Unknown, Value2=10V, ValueDisplayed=10uF
C30: library part CMP-0006626-2, "CAP, CERM, 0.022 uF, 6.3 V, +/- 10%, X7R, 0402", Cap_Case=0402, Manufacturer=MuRata, Supplier Part Number 1=GRM155R70J223KA01D-ND, TempCo=X7R, Tolerance_%=10%, Value1=Unknown, Value2=6.3V, ValueDisplayed=0.022uF
C36 C40 C46 C49 C51 C55: library part CMP-0079153-1, "CAP, CERM, 10 µF, 10 V,+/- 10%, X7R, AEC-Q200 Grade 1, 0805", Cap_Case=0805, Manufacturer=MuRata, Supplier Part Number 1=490-12646-1-ND, TempCo=X7R, Tolerance_%=10%, Value2=10V, ValueDisplayed=10µF
C37 C38 C39 C41 C43 C44 C47 C48 C50 C52 C54: library part CMP-0006659-2, "CAP, CERM, 0.1 uF, 25 V, +/- 10%, X7R, 0402", Cap_Case=0402, Manufacturer=MuRata, Supplier Part Number 1=490-10698-1-ND, TempCo=X7R, Tolerance_%=10%, Value1=Unknown, Value2=25V, ValueDisplayed=0.1uF
C56: library part CMP-0006351-2, "CAP, CERM, 0.1 uF, 16 V, +/- 10%, X7R, 0402", Cap_Case=0402, Manufacturer=MuRata, Supplier Part Number 1=490-4759-2-ND, TempCo=X7R, Tolerance_%=10%, Value1=Unknown, Value2=16V, ValueDisplayed=0.1uF
FID1 FID2 FID3: library part CMP-0077181-1, "Fiducial mark.  There is nothing to buy or mount.", Manufacturer=N/A
J1: library part CMP-0092218-1, "FAKRA-HF STRAIGHT PLUG for PCB", Current_A=1A, Dielectric Material=HTN, Frequency_Fixed=6GHz, Manufacturer=Rosenberger, Operating Temperature Range="-40°C to +105°C", Voltage_V=335V
L1 L2 L3: library part CMP-0003349-2, "Ferrite Bead, 1500 ohm @ 100 MHz, 0.5 A, 0603", Manufacturer=MuRata, Supplier Part Number 1=490-5216-1-ND, Value1="0.5 ohm", Value2=0.5A, ValueDisplayed="1500 ohm"
L4: library part CMP-0058702-1, "Inductor, Wirewound, Ferrite, 10 uH, 0.81 A, 0.288 ohm, AEC-Q200 Grade 1, SMD", Manufacturer=MuRata, Supplier Part Number 1=81-LQH3NPZ100MJRL, Value1="0.288 ohm", Value2=0.81A, ValueDisplayed=10uH
L5: library part CMP-0003343-2, "Ferrite Bead, 1000 ohm @ 100 MHz, 0.4 A, 0603", Manufacturer=MuRata, Supplier Part Number 1=490-1015-1-ND, Value1="0.5 ohm", Value2=0.4A, ValueDisplayed="1000 ohm"
L6: library part CMP-0081093-1, "Inductor, Shielded, Metal Composite, 1.5 µH, 2.3 A, 0.11 ohm, AEC-Q200 Grade 0, SMD", Manufacturer=TDK, Supplier Part Number 1=445-174575-1-ND, Value1="0.11 ohm", Value2=2.3A, ValueDisplayed=1.5µH
L7 L8: library part CMP-0081092-1, "Inductor, Shielded, Metal Composite, 1 µH, 3.1 A, 0.06 ohm, AEC-Q200 Grade 0, SMD", Manufacturer=TDK, Supplier Part Number 1=445-174574-1-ND, Value1="0.06 ohm", Value2=3.1A, ValueDisplayed=1µH
L9 L10 L11: library part CMP-0003316-1, "Ferrite Bead, 1000 ohm @ 100 MHz, 0.35 A, 0402", Manufacturer=MuRata, Supplier Part Number 1=490-5442-1-ND, Value1="0.49 ohm", Value2=0.35A, ValueDisplayed="1000 ohm"
L12 L13: library part CMP-0084741-1, "Ferrite Bead, 600 ohm @ 100 MHz, 0.3 A, 0402", Manufacturer=MuRata, Value1="0.95 ohm", Value2=0.3A, ValueDisplayed="600 ohm"
L14: library part CMP-0003312-1, "Ferrite Bead, 220 ohm @ 100 MHz, 0.45 A, 0402", Manufacturer=MuRata, Supplier Part Number 1=490-5178-1-ND, Value1="0.29 ohm", Value2=0.45A, ValueDisplayed="220 ohm"
Logo1: library part CMP-0074838-1, "Texas Instrument Corporate Signature"
Logo2: library part CMP-0074847-1, "FCC_disclaimer"
R1: library part CMP-0022449-4, "RES, 4.02 k, 1%, 0.1 W, AEC-Q200 Grade 0, 0603", Manufacturer=Vishay-Dale, Power_W=100mW, Supplier Part Number 1=541-4.02KHCT-ND, TempCo="100 ppm/C", Tolerance_%=1%, Value2=0.1W, Value_Code=4k02, ValueDisplayed=4.02k
R2 R3 R4 R5: library part CMP-0027004-2, "RES, 0, 5%, 0.063 W, 0402", Manufacturer="Yageo America", PartNumber=RC0402JR-070RL, Power_W=63mW, Supplier Part Number 1=311-0.0JRCT-ND, TempCo="200 ppm/C", Tolerance_%=5%, Value2=0.063W, Value_Code=0000, ValueDisplayed=0
R6 R7: library part CMP-0026856-5, "RES, 1.5 k, 5%, 0.063 W, AEC-Q200 Grade 0, 0402", Manufacturer=Vishay-Dale, Power_W=63mW, Supplier Part Number 1=541-1.5KJCT-ND, TempCo="200 ppm/C", Tolerance_%=5%, Value2=0.063W, Value_Code=1k50, ValueDisplayed=1.5k
R8: library part CMP-0026404-2, "RES, 49.9, 1%, 0.063 W, AEC-Q200 Grade 0, 0402", Manufacturer=Vishay-Dale, Power_W=63mW, Supplier Part Number 1=541-49.9LCT-ND, TempCo="100 ppm/C", Tolerance_%=1%, Value2=0.063W, Value_Code=49R9, ValueDisplayed=49.9
R9 R10 R11 R12 R13 R17 R18 R19 R20 R21 R22 R23: library part CMP-0026822-3, "RES, 0, 5%, 0.063 W, AEC-Q200 Grade 0, 0402", Manufacturer=Vishay-Dale, Power_W=63mW, Supplier Part Number 1=541-0.0JCT-ND, TempCo="200 ppm/C", Tolerance_%=5%, Value2=0.063W, Value_Code=0000, ValueDisplayed=0
R14: library part CMP-0026825-5, "RES, 10 k, 5%, 0.063 W, AEC-Q200 Grade 0, 0402", Manufacturer=Vishay-Dale, Power_W=63mW, Supplier Part Number 1=541-10KJCT-ND, TempCo="200 ppm/C", Tolerance_%=5%, Value2=0.063W, Value_Code=10k0, ValueDisplayed=10k
R15: library part CMP-0026367-2, "RES, 40.2 k, 1%, 0.063 W, AEC-Q200 Grade 0, 0402", Manufacturer=Vishay-Dale, Power_W=63mW, Supplier Part Number 1=541-40.2KLCT-ND, TempCo="100 ppm/C", Tolerance_%=1%, Value2=0.063W, Value_Code=40k2, ValueDisplayed=40.2k
R16: library part CMP-0026366-2, "RES, 402, 1%, 0.063 W, AEC-Q200 Grade 0, 0402", Manufacturer=Vishay-Dale, Power_W=63mW, Supplier Part Number 1=541-402LCT-ND, TempCo="100 ppm/C", Tolerance_%=1%, Value2=0.063W, Value_Code=402R, ValueDisplayed=402
R24: library part CMP-0026997-2, "RES, 22, 5%, 0.1 W, AEC-Q200 Grade 0, 0402", Manufacturer=Panasonic, Power_W=100mW, Supplier Part Number 1=P22JCT-ND, TempCo="200 ppm/C", Tolerance_%=5%, Value2=0.1W, Value_Code=22R0, ValueDisplayed=22
R25: library part CMP-0026992-3, "RES, 0, 5%, 0.1 W, AEC-Q200 Grade 0, 0402", Manufacturer=Panasonic, Power_W=100mW, Supplier Part Number 1=P0.0JCT-ND, TempCo="600 ppm/C", Tolerance_%=5%, Value2=0.1W, Value_Code=0000, ValueDisplayed=0
U1: library part CMP-0092635-1, "Highly integrated power management IC for automotive camera modules", Manufacturer="Texas Instruments", Max Supply Voltage=18.3V, Min Supply Voltage=4V, Nominal Supply Current=10mA, Operating Temperature Range="-40°C to +150°C", Output Voltage=2.5-4/0.9-1.9/1.8-3.3V
U2: library part CMP-0084098-1, "2MP MIPI CSI-2 FPD-Link III Serializer for 2MP/60fps Cameras and RADAR, RHB0032P (VQFN-32)", Alternate Manufacturer="Texas Instruments", Alternate PartNumber=DS90UB953TRHBTQ1, Operating Temperature Range="-40 to 105 C", Rating=Automotive
U3: library part CMP-0092734-1, "CMOS Image Sensor, Digital, 8.3 MP, 1/2-inch, High-Resolution", Manufacturer="On Semiconductor", Max Supply Voltage=3V, Min Supply Voltage=1.14V, Operating Supply Current=1500mA, Operating Temperature Range="-40°C to +125°C"
Y1: library part CMP-0087863-1, "MEMS OSC XO 24.0000MHZ CMOS SMD", Frequency_Fixed=24MHz, Frequency Stability=25ppm, Manufacturer=Microchip
ZZ1: library part CMP-0077236-1
ZZ2: library part CMP-0077237-1
ZZ3: library part CMP-0077238-1

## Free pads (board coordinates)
  round 62.99 hole 62.99 unplated paste+0: MT1(-35.43,397.64) MT2(830.71,397.64)

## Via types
v1: diameter 10, hole 6, Top Layer to Bottom Layer, tented both sides, 79 vias
v2: diameter 16, hole 7.87, Top Layer to Bottom Layer, tented both sides, 61 vias
v3: diameter 19.68, hole 7.87, Top Layer to Bottom Layer, 17 vias

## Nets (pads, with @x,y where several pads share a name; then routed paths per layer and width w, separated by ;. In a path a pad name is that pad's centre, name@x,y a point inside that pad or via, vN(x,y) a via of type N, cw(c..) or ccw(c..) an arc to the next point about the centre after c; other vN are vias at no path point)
1V2: C45.2 C46.1 C47.1 C48.1 C51.1 C52.1 L13.1 R4.2 U1.14 U3.A4 U3.A7 U3.B6 U3.C1 U3.C8 U3.C9 U3.D1 U3.D12 U3.E10 U3.E12 U3.F1 | length 3626.5
  Top Layer w5: v1@437.32,289 437.32,267.26 446.92,257.65 459.66,257.65 466.01,264 475.76,264 U3.A4@484.79,273.03 ; 563.15,383.64 563.15,414.38
  Top Layer w8: 390.3,248.3 U3.A7@390.3,273.03
  Top Layer w10: C46.1@102,446.63 105.62,450.25 C45.2@156,450.25 181.58,450.25 U3.E12@232.82,399.01 U3.D12@232.82,367.51 ; C47.1@319.68,196 319.68,167.32 368,119 402,119 ; C47.1@320,197 320,232.03 329.97,242 384,242 390.3,248.3 ; v2@384.82,57.18 402,74.36 402,119 ; L13.1@428,119 402,119 ; 563.15,383.64 U3.D1@579.28,367.51 ; 563.15,414.38 U3.F1@579.28,430.51
  Top Layer w12: C46.1@102,446.63 106.92,446.63 126.79,426.77 131.23,426.77 v2(132,426) ; U3.E10@295.81,399.01 296.01,399.01 v2(312,415) ; U3.C9@327.31,336.02 328.02,336.02 v2(344,352) 358.8,337.2 U3.C8@358.8,336.02 ; U3.B6@421.79,304.52 v1@437.32,289 ; U3.C1@579.28,336.02 U3.D1@579.28,367.51 ; U3.F1@579.28,430.51 601.57,430.51 628,456.94 628,477.06 639.99,489.06 640.4,489.06 652.35,501 C48.1@654.32,501 654.32,503.94 C51.1@694,543.63
  Top Layer w16: v2(363,59) v2(383,59) ; v2(682,577) 682,555.63 C51.1@694,543.63
  Signal Layer 1 w5: v1(237.53,214.47) 204,180.95 204,129 224,109 313,109 v2(363,59)
  Signal Layer 1 w16: v2(363,59) v2(383,59)
  Signal Layer 3 w16: 321,504 341,484 ; 350,483 370,503 ; 405.43,101.43 v2(363,59) v2(383,59) 407.75,83.75 ; 550,506 570,506 ; 573,484 573,504
  Signal Layer 3 w18: 407,212.28 463.72,269 484.5,269 571,355.5
  Signal Layer 3 w20: v2(132,426) 118,426 67,477 67,488.41 66.94,488.47 66.94,507.53 67,507.59 67,563 103,599 207,599 302,504 321,504 345.16,504 ; v2(312,415) 345.16,448.16 345.16,504 ; 407,86 407,212.28 ; 571,355.5 571,480.76 559.88,491.88 ; v2(682,577) 652,547 617.53,547 616.53,546 614,546 559.88,491.88 ; 345.16,504 547.76,504 559.88,491.88
  Signal Layer 4 w16: v2(363,59) v2(383,59)
  Bottom Layer w5: U1.14@210.02,198.72 223.72,198.72 240,215 239,216 v1(237.53,214.47) v1(237.53,214.47)
  Bottom Layer w16: v2(344,352) 417.63,278.37 C52.1@417.63,270.67 ; R4.2@363,98.78 v2(363,59) v2(383,59) 397.14,73.14 ; 367,74 411.3,74 432,94.7 432,255.63 417.63,270 C52.1@417.63,270.67 ; v1@436.3,289.33 C52.1@417.63,270.67 ; v1@436.63,289 v1(438,289)
1V8: C49.1 C50.1 L9.1 L10.1 L11.1 L14.1 R3.2 R6.2 R7.2 R17.2 R18.2 R19.2 U1.17 U1.18 U3.A3 U3.A6 U3.E1 U3.E11 U3.F12 | length 3931.8
  Top Layer w8: C50.1@450,95.32 C50.1@456.32,89 456.32,109.32
  Top Layer w10: 199,533 199,464.32 U3.F12@232.82,430.51 U3.E11@264.31,399.01 ; U3.A6@421.79,273.03 421.79,257.21 450,229 C50.1@450,95.32
  Top Layer w12: C49.1@106,587 145,587 199,533 ; 456.32,109.32 496,149 496,252.74 U3.A3@516.28,273.03 ; U3.E1@579.28,399.01 593.27,413 694.13,413 699.13,418 699.5,418 715.87,418 715.93,417.93 758,460 v2(758,519) ; R7.2@719,174 R7.2@722,174
  Top Layer w16: C49.1@106,587 v2(140,553) ; v2(423,56) v2(443,56) 456.32,69.32 C50.1@456.32,89 ; R7.2@722,174 741,155 v2@743,155 ; R6.2@723,135 v2@743,155 ; v2(745,155) v2@743,155
  Top Layer w20: R3.2@427,89 C50.1@456.32,89
  Signal Layer 1 w5: v1(236,136) 361.65,136 423,74.65 v2(423,56)
  Signal Layer 1 w16: v2(423,56) v2(443,56)
  Signal Layer 3 w16: 219,360 239,380 ; 219,407 239,387 ; 403,36 v2(423,56) ; v2(443,56) 463,36
  Signal Layer 3 w18: 684.25,279.25 709,304
  Signal Layer 3 w20: v2(140,553) 190,553 219,524 219,407 219,381 ; v1(249,383) 221,383 219,381 ; v2@424,54 v2@442,54 ; 460,36 403,36 344,36 326,54 326,124 304,146 304,236 219,321 219,360 219,381 ; 463,36 613,36 646.78,69.78 ; v2(632,521) 632,350 679,303 ; 678,101 646.78,69.78 ; 680,115.22 691.11,104 ; 689,104 691.11,104 ; 702,93 691.11,104 ; 707,104 691.11,104 ; v2(745,155) 745,135.78 679,69.78 ; v2(758,519) 758,387 739,368 739,335 707,303 679,303 ; 646.78,69.78 679,69.78 ; 679,69.78 679,303
  Signal Layer 4 w16: v2(423,56) v2(443,56)
  Bottom Layer w8: U1.18@210.02,119.98 U1.17@210.02,139.67 232.33,139.67 v1(236,136)
  Bottom Layer w12: L14.1@249,363 v1(249,383) ; L10.1@625.14,545.14 632,538.28 v2(632,521) ; R17.2@686,753 R19.2@686,714 686,697.6 R18.2@708.6,675 ; R18.2@702,675 R18.2@708.6,675 ; v2@748.27,154.77 762,168.5 L9.1@762,173 ; L11.1@758,507 v2(758,519) 742,535 742,641.6 R18.2@708.6,675
2V8: C35.2 C36.1 C37.1 C38.1 C39.1 C40.1 C41.1 L12.1 R5.2 U3.B1 U3.C2 U3.D11 U3.G1 U3.G12 | length 2980.5
  Top Layer w5: 222,352 248.8,352 U3.D11@264.31,367.51
  Top Layer w10: C41.1@214.32,568 234,587.68 C35.2@234,599.25 ; C41.1@214.94,568 214.94,553.68 215,553.63 215,526.37 214.94,526.32 214.94,479.88 U3.G12@232.82,462
  Top Layer w12: v2(36,348) 37,348 38.68,349.68 C39.1@162,349.68 164.32,352 222,352 ; v2@59,79 59,116 80,136 R5.2@88,136 ; C41.1@214.32,568 214.94,568 C41.1@217.58,570.64 ; C35.2@234,599.25 193.38,599.25 C40.1@175,617.63 175,647.68 184.32,657 v2(218,657) 262.72,657 L12.1@291.09,628.63 ; U3.C2@547.78,336.02 U3.B1@579.28,304.52 603.52,304.52 630.68,331.68 650,331.68 C38.1@650,337.68 650,361.63 C36.1@668,379.63 668.37,380 C36.1@669.37,379 ; U3.G1@579.28,462 602,484.73 602,547.32 C37.1@623.68,569
  Top Layer w16: v2@57,79 v2(53,75) v2(34,75) 34,76 57.04,99.04 ; v2(607,580) 612.68,580 623.68,569 C37.1@624,569.32 ; C36.1@669.37,379 675.37,385 684.37,376 707.37,399 v2(707,399)
  Signal Layer 1 w16: v2(34,75) v2(53,75)
  Signal Layer 3 w12: 218,638 v2(218,657)
  Signal Layer 3 w16: v2(34,75) v2(53,75) 66,88 66,333.44 51.44,348 v2(36,348) ; 198,637 199,638 v2(218,657) 237,638 238,637 ; 558.58,590 578.58,590 ; 567.5,606.5 594,580 v2(607,580) ; 587,592.35 587,602.35 ; 587,612.35 587,602.35 ; 607,622.35 606.65,622 587,602.35
  Signal Layer 3 w20: 51.44,349.97 51.44,383.56 42,393 42,478.05 41.94,478.12 41.94,517.88 42,517.95 42,611 88,657 162,657 181,638 199,638 218,638 237,638 267,638 372,533 494,533 567.5,606.5 583,622 606.65,622 697,622 729,590 729,539 686,496 686,420 v2(707,399)
  Signal Layer 4 w16: v2(34,75) v2(53,75)
3V3: C7.1 C8.1 C10.1 R2.2 U1.6 U1.15 U1.21 U1.23 | length 1657.3
  Top Layer w16: v2(106,75) C10.1@133,75
  Signal Layer 1 w5: v1(35,248) 63,248 175,360 v2(175,501) ; v2@177,521 v2@180,518
  Signal Layer 1 w19.68: v2(155,521) v2(175,521) v2(175,501)
  Signal Layer 1 w20: v2(155,521) v2(175,501)
  Signal Layer 3 w14: v2(106,75) 112,81 112,229 126.17,243.17
  Signal Layer 3 w16: 159,241 189,241
  Signal Layer 3 w19.68: v2(155,521) v2(175,521) v2(175,501)
  Signal Layer 3 w20: 128,243 160.05,243 ; v2(155,521) v2(175,501) ; 158.66,243.17 174,258.51 ; v2(162,39) 162,81.67 210,129.67 210,222.51 ; v2@174,504 174,258.51 ; 227.49,240 210,222.51 ; v2(276,224) 260,240 192.51,240 ; 174,258.51 192.51,240 ; 192.51,240 210,222.51
  Signal Layer 4 w19.68: v2(155,521) v2(175,521) v2(175,501)
  Signal Layer 4 w20: v2(155,521) v2(175,501)
  Bottom Layer w5: v1(35,248) 35,236.93 51.1,220.83 U1.6@55.49,216.44
  Bottom Layer w8: U1.23@105.68,94.39 U1.23@106,94.08
  Bottom Layer w10: v2(106,75) U1.23@106,94.08 ; C7.1@145,43 145.06,43.06 U1.21@145.05,94.39 ; U1.15@210.02,179.04 234.04,179.04 260,205 C8.1@260,213
  Bottom Layer w16: C7.1@149,39 v2(162,39) ; C8.1@260,213 271,224 v2(276,224)
  Bottom Layer w20: C7.1@145,43 C7.1@149,39
CLK: R24.2 R25.2 U3.D7 | length 613.9
  Top Layer w5: v1(375,383) 375,382.81 U3.D7@390.3,367.51 ; v1(718,352) 718,344 718,332 R25.2@719,331
  Signal Layer 2 w5: v1(375,383) 359.66,398.34 359.66,483.66 389.86,513.86 542.63,513.86 543.49,513 544.28,513 566.11,491.17 566.26,491.17 584.43,473 584.57,473 705.57,352 v1(718,352)
  Bottom Layer w5: R24.2@375,396 R24.2@384,396
  Bottom Layer w8: v1(375,383) 375,387 R24.2@384,396
CSI0_CLK_N: U2.6 U3.B10 | length 645.9
  Top Layer w3: U3.B10@295.81,304.52 U3.B10@297.02,304.52
  Top Layer w5: U3.B10@297.02,304.52 v1(312.5,320)
  Signal Layer 2 w3: v1(312.5,320) cw(c321.38,320) 315.12,326.31 cw(c321.66,319.73) 321.66,329 327,329 327.4,329 cw(c327.4,327) 329.4,327 329.4,316 ccw(c331.4,316) 331.4,314 335.4,314 ccw(c335.4,316) 337.4,316 337.4,327 cw(c339.4,327) 339.4,329 341.4,329 ; 341,329 347,329 cw(c347,326) 349.12,328.12 cw(c347,326) 350,326 350,310.97 ccw(c360.92,310.97) 353.2,303.24 ; 353.22,303.22 ccw(c361,311) 361,300 363.02,300 ccw(c363.02,310.94) 370.76,303.2 ; 370.78,303.22 ccw(c363,311) 374,311 374,327 cw(c377,327) 374.88,329.12 cw(c377,327) 377,330 379,330 cw(c379,327) 381.12,329.12 cw(c379,327) 382,327 382,309 ccw(c388.17,309) 383.8,304.65 385.22,303.22 ccw(c393,311) 393,300 395.02,300 ccw(c395.02,310.94) 402.76,303.2 ; 402.78,303.22 ccw(c395,311) 406,311 406,327 cw(c409,327) 406.88,329.12 cw(c409,327) 409,330 411,330 cw(c411,327) 413.12,329.12 cw(c411,327) 414,327 414,311 ; 414,310.97 ccw(c424.92,310.97) 417.2,303.24 ; 417.22,303.22 ccw(c425,311) 425,300 427.02,300 ccw(c427.02,310.94) 434.76,303.2 ; 434.78,303.22 ccw(c427,311) 438,311 438,327 cw(c441,327) 438.88,329.12 cw(c441,327) 441,330 443,330 cw(c443,327) 445.12,329.12 cw(c443,327) 446,327 446,311 ; 446,310.97 ccw(c456.92,310.97) 449.2,303.24 ; 449.22,303.22 ccw(c457,311) 457,300 480,300 480.4,300 cw(c480.4,298) 482.4,298 482.4,287 ccw(c484.4,287) 484.4,285 488.4,285 ccw(c488.4,287) 490.4,287 490.4,298 cw(c492.4,298) 492.4,300 494.4,300 531.8,300 538,300 cw(c538,297) 540.12,299.12 cw(c538,297) 541,297 541,293.03 cw(c537.93,293.03) 540.1,290.86 cw(c538.03,292.92) 538.03,290 ; v1(472,249) ccw(c473.74,249) 472.51,247.77 477.28,243 497.11,243 ccw(c497.09,245.91) 500,245.87 500,246.08 500,255 500,257.04 ccw(c498,257.04) 498,259.04 487,259.04 cw(c487,261.04) 485,261.04 485,265.04 cw(c487,265.04) 487,267.04 498,267.04 ccw(c498,269.04) 500,269.04 500,275.04 500,279.04 cw(c510.92,279.04) 503.2,286.75 503.24,286.79 cw(c510.98,279.06) 510.98,290 538,290
  Bottom Layer w5: v1(472,249) 472.47,248.53 U2.6@493.51,248.53
CSI0_CLK_P: U2.5 U3.A10 | length 643.5
  Top Layer w3: U3.A10@295.81,273.03 U3.A10@297.02,273.03
  Top Layer w5: U3.A10@297.02,273.03 v1(312.5,288.5)
  Signal Layer 2 w3: v1(312.5,288.5) cw(c313.69,289.7) 312,289.7 312,305.9 ccw(c309,305.93) 309.72,308.84 cw(c312.5,320) 308.1,330.62 309.42,331.95 cw(c321.62,319.75) 321.62,337 348.34,337 cw(c348.34,329.24) 353.83,334.73 354.82,333.74 cw(c347.14,326.06) 358,326.06 ; 358,327.06 358,326.06 ; 369.22,334.78 ccw(c377,327) 366,327 366,311 cw(c363,311) 365.12,308.88 cw(c363,311) 363,308 361,308 cw(c361,311) 358.88,308.88 cw(c361,311) 358,311 358,326.06 ; 369.25,334.8 cw(c376.96,327.09) 376.96,338 381,338 cw(c381,331.83) 385.35,336.2 386.8,334.76 cw(c379.08,327.03) 390,327.03 390,311 ccw(c393,311) 390.88,308.88 ccw(c393,311) 393,308 395,308 ccw(c395,311) 397.12,308.88 ccw(c395,311) 398,311 398,327 cw(c409,327) 401.22,334.78 ; 401.25,334.8 cw(c408.96,327.09) 408.96,338 411.03,338 cw(c411.03,327.08) 418.76,334.8 418.8,334.76 cw(c411.08,327.03) 422,327.03 422,311 ccw(c425,311) 422.88,308.88 ccw(c425,311) 425,308 427,308 ccw(c427,311) 429.12,308.88 ccw(c427,311) 430,311 430,327 cw(c441,327) 433.22,334.78 ; 433.25,334.8 cw(c440.96,327.09) 440.96,338 443.03,338 cw(c443.03,327.08) 450.76,334.8 450.8,334.76 cw(c443.08,327.03) 454,327.03 454,311 ccw(c457,311) 454.88,308.88 ccw(c457,311) 457,308 538,308 ; v1(472,229.32) cw(c473.74,229.32) 472.51,230.55 476.96,235 497.09,235 ccw(c497.09,245.91) 508,245.99 508,279 cw(c511,279) 508.88,281.12 cw(c511,279) 511,282 538,282 ; 538.04,282 ccw(c538.04,292.9) 545.75,285.19 ccw(c537.9,293.04) 549,293.04 549,297 ccw(c537.99,297) 545.78,304.78 ; 538.03,308 cw(c538.03,297.08) 545.76,304.8
  Bottom Layer w5: v1(472,229.32) 472.47,228.84 U2.5@493.51,228.84
CSI0_D0_N: U2.4 U3.B8 | length 641.6
  Top Layer w3: U3.B8@358.8,304.2 U3.B8@358.8,304.52
  Top Layer w5: U3.B8@358.8,304.2 v1(374,289)
  Signal Layer 2 w3: v1(374,289) 374,280 ccw(c377,280) 374.88,277.88 ccw(c377,280) 377,277 383.03,277 cw(c383.03,266.08) 390.76,273.8 390.8,273.76 cw(c383.08,266.03) 394,266.03 394,169 ccw(c397,169) 394.88,166.88 ccw(c397,169) 397,166 399,166 ccw(c399,169) 401.12,166.88 ccw(c399,169) 402,169 402,266 cw(c413,266) 405.22,273.78 ; 405.25,273.8 cw(c412.96,266.09) 412.96,277 415.03,277 cw(c415.03,266.08) 422.76,273.8 422.8,273.76 cw(c415.08,266.03) 426,266.03 426,169 ccw(c429,169) 426.88,166.88 ccw(c429,169) 429,166 431,166 ccw(c431,169) 433.12,166.88 ccw(c431,169) 434,169 434,266 cw(c445,266) 437.22,273.78 ; 437.25,273.8 cw(c444.96,266.09) 444.96,277 447.03,277 cw(c447.03,266.08) 454.76,273.8 454.8,273.76 cw(c447.08,266.03) 458,266.03 458,207 ccw(c461,207) 458.88,204.88 ccw(c461,207) 461,204 466,204 471.63,209.63 v1(472,209.63)
  Bottom Layer w3: v1(472,209.63) v1@472.47,209.16
  Bottom Layer w5: v1@472.47,209.16 U2.4@493.51,209.16
CSI0_D0_P: U2.3 U3.A8 | length 642.3
  Top Layer w3: U3.A8@358.8,272.2 U3.A8@358.8,273.03
  Top Layer w5: U3.A8@358.8,272.2 v1(374,257)
  Signal Layer 2 w3: v1(374,257) 374,266 cw(c377,266) 374.88,268.12 cw(c377,266) 377,269 383,269 cw(c383,266) 385.12,268.12 cw(c383,266) 386,266 386,168.97 ccw(c396.92,168.97) 389.2,161.24 ; 389.22,161.22 ccw(c397,169) 397,158 399.02,158 ccw(c399.02,168.94) 406.76,161.2 ; 406.78,161.22 ccw(c399,169) 410,169 410,266 cw(c413,266) 410.88,268.12 cw(c413,266) 413,269 415,269 cw(c415,266) 417.12,268.12 cw(c415,266) 418,266 418,168.97 ccw(c428.92,168.97) 421.2,161.24 ; 421.22,161.22 ccw(c429,169) 429,158 431.02,158 ccw(c431.02,168.94) 438.76,161.2 ; 438.78,161.22 ccw(c431,169) 442,169 442,266 cw(c445,266) 442.88,268.12 cw(c445,266) 445,269 447,269 cw(c447,266) 449.12,268.12 cw(c447,266) 450,266 450,206.97 ccw(c460.92,206.97) 453.2,199.24 ; 453.22,199.22 ccw(c461,207) 461,196 466,196 472,190 v1(472,189.94)
  Bottom Layer w5: v1(472,189.94) 472.47,189.47 U2.3@493.51,189.47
